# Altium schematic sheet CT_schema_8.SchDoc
size 254 x 194 mm
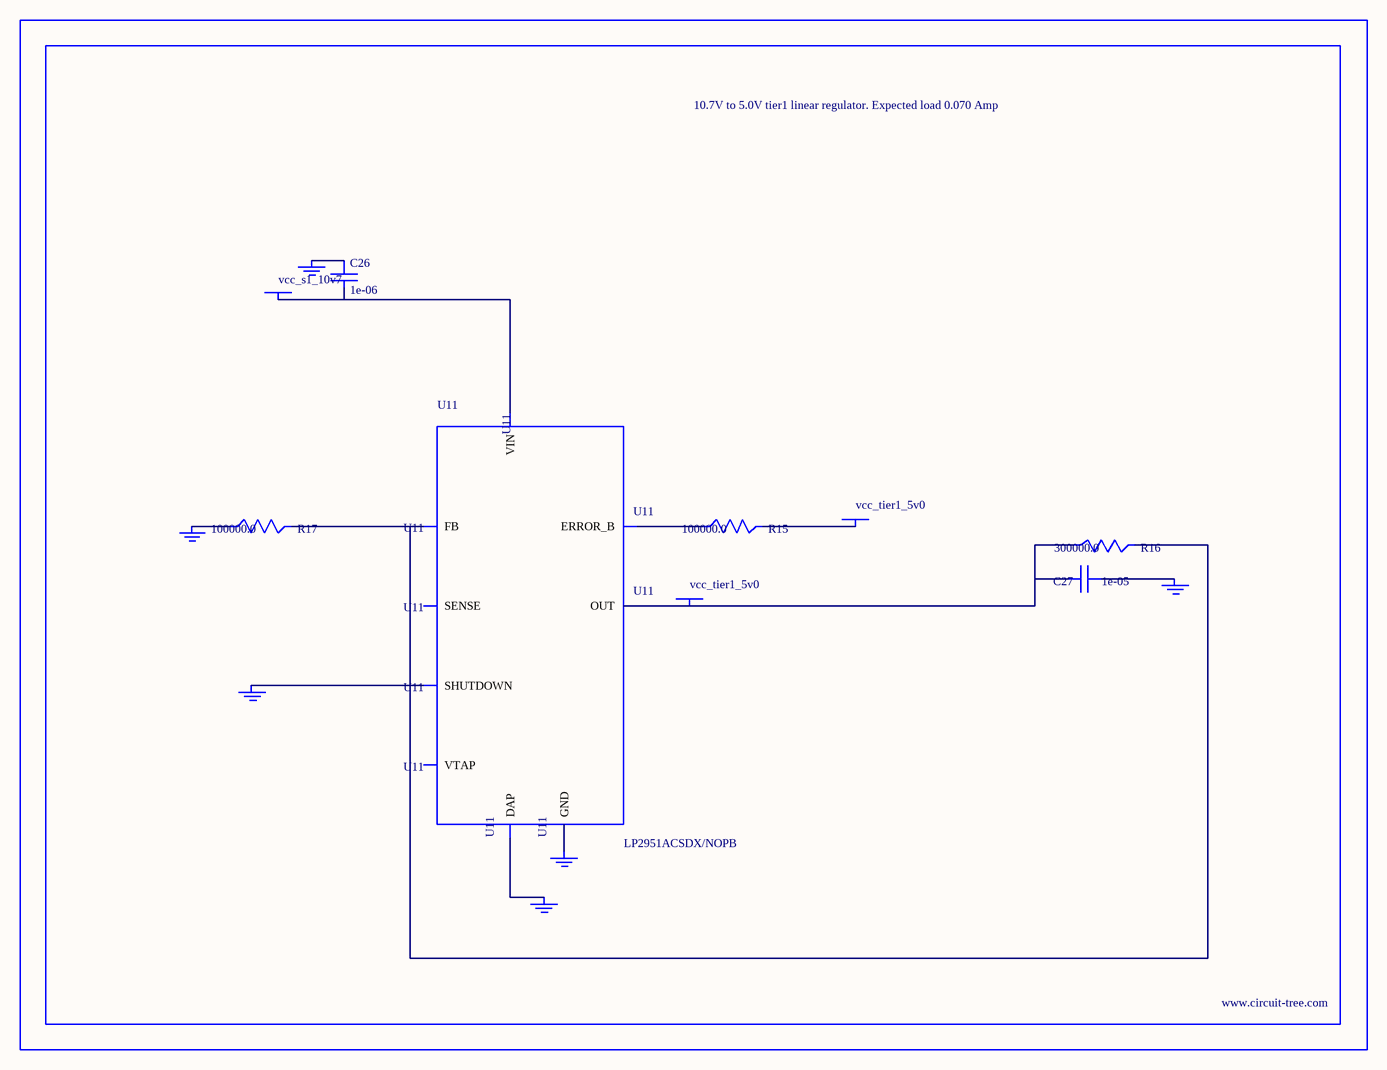
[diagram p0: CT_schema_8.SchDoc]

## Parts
BORDER7  (no value)
C26  1e-06  [C0603]
C27  1e-05  [C1210]
GND_INSTANCE_7_0  (no value)
GND_INSTANCE_7_1  (no value)
GND_INSTANCE_7_2  (no value)
GND_INSTANCE_7_3  (no value)
GND_INSTANCE_7_4  (no value)
GND_INSTANCE_7_5  (no value)
POWER_INSTANCE_7_0  vcc_tier1_5v0
POWER_INSTANCE_7_1  vcc_s1_10v7
POWER_INSTANCE_7_2  vcc_tier1_5v0
R15  100000.0  [R0603]
R16  300000.0  [R0603]
R17  100000.0  [R0603]
U11  LP2951ACSDX/NOPB  [WSON-8]

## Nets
NetC26_1: C26.1 GND_INSTANCE_7_3.0(GND)
NetC26_2: C26.2 POWER_INSTANCE_7_1.0(PWR) U11.8(VIN)
NetC27_1: C27.1 GND_INSTANCE_7_0.0(GND)
NetC27_2: C27.2 POWER_INSTANCE_7_2.0(PWR) R16.1 U11.1(OUT)
NetGND_INSTANCE_7_1_0: GND_INSTANCE_7_1.0(GND) U11.3(SHUTDOWN)
NetGND_INSTANCE_7_2_0: GND_INSTANCE_7_2.0(GND) R17.1
NetGND_INSTANCE_7_4_0: GND_INSTANCE_7_4.0(GND) U11.PAD(DAP)
NetGND_INSTANCE_7_5_0: GND_INSTANCE_7_5.0(GND) U11.4(GND)
NetPOWER_INSTANCE_7_0_0: POWER_INSTANCE_7_0.0(PWR) R15.2
NetR15_1: R15.1 U11.5(ERROR_B)
NetR16_2: R16.2 R17.2 U11.7(FB)

Not connected (* = marked no-connect by the designer): U11 2(SENSE) 6(VTAP)

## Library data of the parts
BORDER7 = BORDER_PAGE7
C26 = C0603C105K3RACTU
C27 = GRM32DR61E106MA12L
GND_INSTANCE_7_0-GND_INSTANCE_7_5 = GND
POWER_INSTANCE_7_0-POWER_INSTANCE_7_2 = PWR
R15 R17 = RC0603JR-07100KL
R16 = RC0603JR-07300KL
